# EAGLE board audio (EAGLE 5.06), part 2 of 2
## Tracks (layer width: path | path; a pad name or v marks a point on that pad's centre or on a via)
GND  (via drill 0.8)  (1 unrouted)
  Top 0.254: v49.37,12.53 49.02,12.53 C25.2 48.86,12.69 48.1,12.69
  Top 0.305: 13.49,32.85 13.65,32.85 14.28,33.49 15.87,33.49 15.87,31.9 14.44,31.9 13.65,32.7 | 64.61,42.06 64.61,40 | 72.54,17.46 | 72.54,17.46 73.02,16.98 | 40.16,12.38 40.32,12.38 40.16,12.38 | 40.16,12.38 40,12.22 | 40.16,12.38 40,12.53
  Top 0.406: 71.75,27.46 70.48,27.46 70.32,27.3 70.32,26.35 70.64,26.03 | 26.66,6.5 | C40.2 26.66,6.5 | 70.64,26.03 | 72.7,23.96 70.64,26.03 | 73.02,16.98 75.56,16.98 75.56,16.03 | 25.39,0.47 | 22.38,7.45 22.38,6.66 | 22.38,6.66 22.38,3.49 | 22.38,3.49 | 22.38,3.49 25.39,0.47 | 22.38,3.49 22.38,0.47 | 22.38,6.66 22.86,7.14 | 22.38,6.66 21.74,7.3 | R19.1 43.18,12.38 43.02,12.38 | v39.37,12.38 40.32,12.38 43.02,12.38 | 43.02,12.38 44.92,12.38 45.4,11.9 47.3,11.9 48.1,12.69 48.1,13.33 59.05,13.33 | C41.1 50,19.68 IC7.1 49.11,19.62 v49.53,19.2
  Top 0.61: 31.59,38.09 31.59,30.95 30.79,30.16 | 30.79,30.16 | 30.79,30.16 30.63,30 28.25,30 28.25,32.85 30.63,32.85 31.11,33.33 | 47.78,42.06 47.78,40.32 47.94,40.16 51.27,40.16 51.27,42.54 51.75,43.01 | IC2.8 28.99,31.32 28.89,31.43 IC2.7 29.05,31.43 28.99,31.48 IC2.6 30.63,32.7 31.11,33.17 31.11,33.33 | 15.08,32.85 C3.2 | 15.08,32.85 | 8.57,32.85 8.41,32.85 7.77,33.49 | 8.57,32.85 9.2,32.85 | 9.2,32.85 13.49,32.85 15.08,32.85 | 31.11,42.7 31.11,40 | 31.11,40 31.11,33.33 | 50.64,41.11 50.64,41.27 48.89,43.01 51.75,43.01 | 51.75,43.01 63.65,43.01 64.61,42.06 65.4,41.27 C37.2 | C37.2 65.4,40.47 | C17.2 41.4,20.5 41.43,20.47 41.91,20.95 IC7.7 | IC6.5 IC6.12 72.23,28.09 I2C.2 70.96,26.66 73.18,24.44 | IC6.5 72.23,36.66 | 72.23,36.66 | 74.77,36.51 | 74.77,36.51 IC6.3 IC6.2 | IC6.5 74.71,36.56 74.77,36.51 | IC6.2 76.14,36.56 76.19,36.51 | 77.31,36.51 | 77.31,36.51 IC6.1 78.68,36.56 79.21,36.35 C13.1 79.21,36.98 | IC6.2 77.25,36.56 77.31,36.51 | C37.2 65.4,43.01 80.64,43.01 81.12,42.54 81.12,36.19 | 73.18,24.44 IC8.16 | 73.18,24.44 72.7,23.96 72.54,23.81 72.54,17.46 72.54,16.82 | 72.54,16.82 72.54,15.55 | 72.54,15.55 IC8.9 74.77,15.55 | 72.54,16.82 IC8.10 | 72.54,15.55 IC8.8 | 74.77,15.55 C18.- | 74.77,15.55 | R19.1 43.49,11.74 | 40.79,0.79 40.64,0.95 40.16,0.47 25.39,0.47 | C20.2 31.08,3.67 | 3.01,33.97 1.27,33.97 | 3.01,33.97 8.09,33.97 9.2,32.85 | 8.57,32.85 1.9,32.85 1.11,32.06 | 3.01,33.97 1.9,33.97 1.27,34.6 | 81.12,32.22 80.48,31.58 79.21,31.58 79.21,30.47 81.12,30.47 81.43,30.79 81.43,42.38 80.64,43.17 0.95,43.17 0.31,42.54 0.31,19.36 0.79,18.88 4.6,18.88 4.92,19.2 4.92,21.27 4.6,21.58 1.42,21.58 0.47,22.54 | 81.12,35.39 80.32,36.19 77.78,36.19 77.31,35.71
  Top 0.61: 26.98,42.7 26.98,42.06 28.41,40.63 30.47,40.63 31.11,40
  Top 0.813: R8.1 50.64,41.11 | C13.1 80.51,36.79 81.12,36.19 81.12,35.39 81.12,32.22 81.12,31.74 80.48,31.11 80,31.11 79.98,31.08 C12.2 | U$1.P$2 1.27,20.31 0.63,20.95 | 0.63,20.95 | 0.63,20.95 0.47,21.11 0.47,22.54 0.47,27.14 0.95,27.62 0.95,27.46 | 46.64,10.98 46.67,10.95 48.39,12.66 C25.2 | 26.82,6.5 26.35,7.45 22.38,7.45 | 22.06,7.77 22.38,7.45 | 22.38,7.45 16.35,7.45 15.87,7.93 15.87,9.99 | 24.92,7.77 26.03,6.66 26.03,5.87 27.78,5.87 28.57,5.07
  Top 1.016: 6.19,39.84 6.19,38.41 6.03,38.25 1.74,38.25 0.79,37.3 | C25.2 48.89,13.01 | 48.89,13.01 | 48.89,13.01 56.19,13.01 | 56.19,13.01 58.41,13.01 R24.1 | R24.1 | R24.1 | 56.19,13.01 C26.2
  Top 1.27: C32.2 37.62,42.7 | 10.63,27.46 C34.+ C33.- 10.63,11.58 C35.- | C19.1 29.2,3.96 28.89,4.28 28.89,6.5 | C40.2 26.79,6.47 26.82,6.5 28.89,6.5 | C22.2 32.35,11.71 28.89,8.25 28.89,6.5 | 40.79,0.79 46.67,0.79 | 46.67,0.79 48.26,0.79 | 46.67,0.79 58.26,0.79 59.21,1.74 | 59.21,1.74 | 59.21,1.74 59.37,1.9 59.37,3.8 59.53,3.96 64.77,3.96
  Top 1.422: 7.77,33.49 AF_IN1.1 0.79,33.49 | 0.79,33.49 0.79,27.46 0.95,27.46 AF_IN2.1 10.63,27.46 11.74,27.46 12.54,26.66 14.76,26.66 | 37.62,42.7 31.11,42.7 26.98,42.7 1.11,42.7 0.79,42.38 0.79,37.3 0.79,33.49 | 48.41,40.95 48.41,42.7 37.78,42.7 37.62,42.54 C32.2 | 48.41,40.95 C6.1 | R8.1 48.42,40.94 48.41,40.95 | C17.2 41.27,20.47 40.16,20.47 | C17.2 | 40.16,20.47 C16.- | TR1.2 16.35,26.66 14.76,26.66 | C22.2 36.19,11.74 36.83,12.38 v39.37,12.38 | R19.1 44.77,11.73 45.56,10.95 46.19,10.95 | 19.68,7.77 18.57,7.77 16.27,10.07 | 19.68,7.77 20.79,7.77 | 20.79,7.77 22.06,7.77 | L1.5 69.37,6.18 74.77,11.58 C18.- | L1.5 | 40.16,20.47 | v40,18.41 40.16,20.47 | 14.76,26.66 22.38,26.66 22.7,26.35 22.7,22.85 | 22.7,22.85 22.7,21.74 26.51,17.93 26.51,17.61 21.9,17.61 | 16.03,17.61 21.9,17.61 | 16.03,17.61 13.49,17.61 | 16.27,10.07 14.92,11.42 C35.- | C35.- | 16.27,10.07 16.35,10.15 | 16.35,10.15 C36.- | 16.35,10.15 | v39.37,12.38 38.73,13.01 30.79,13.01 25.55,7.77 | 20.79,7.77 24.92,7.77 25.55,7.77 | 25.55,7.77 25.87,7.77 | 19.68,7.77 19.2,7.77 14.76,12.22 14.76,16.34 16.03,17.61 | 22.7,21.11 22.7,22.85 | 22.7,18.41 22.7,21.11 | 22.7,18.41 22.7,17.93 | 21.58,22.06 21.74,22.06 22.7,21.11 | 21.9,17.61 22.7,18.41 | 29.2,3.49 | C19.1 29.2,3.49 | C20.2 29.39,3.67 29.2,3.49 | v39.37,12.38 | v39.37,12.38 38.57,11.58 34.76,11.58 33.97,10.79 | 33.97,10.79 | 33.97,10.79 33.81,10.63 33.81,9.52 30.47,9.52
  Bottom 0.254: v39.37,12.38 39.37,17.61 v40,18.41 | v49.53,19.2 49.53,12.69 v49.37,12.53
N$1
  Top 1.676: C1.- | AF_IN1.2 C1.-
N$2
  Top 1.676: AF_IN2.2 6.82,30 C2.- 2.85,31.11 AF_IN2.2
N$3
  Top 1.016: 12.54,39.2 | 12.54,39.2 D1.C 12.58,39.32 14.12,37.78 R1.1 | D2.A 12.42,39.32 12.54,39.2
  Top 1.422: C1.+ | C1.+ 9.04,39.36 10.63,39.36 | 10.63,39.36 | 10.63,39.36 D2.A
N$4
  Top 0.406: 16.5,40.79 16.35,40.79 15.55,40 14.12,40
  Top 0.61: IC1.2 19.84,40.32 20,40.47 22K.1 19.84,40.47 19.68,40.32 19.68,40.79 16.5,40.79 14.92,40.79 R1.2 | R1.2 | R1.2
N$5
  Top 0.406: 29.84,39.36 27.78,39.36 27.62,39.36 26.03,40.95
  Top 0.61: 25.87,40.95 26.19,40.95 27.78,39.36
N$6
  Top 0.61: IC1.6 18.57,29.84 R4.1
  Top 1.422: R4.1 R3.2
N$7
  Top 0.254: 19.68,32.7 19.68,31.43 21.11,30 21.43,29.68
  Top 0.406: IC1.7 19.84,31.43 21.27,30 R4.2
  Top 0.61: IC2.2 27.46,37.78 26.98,37.3 26.98,32.22 | 26.98,32.22 24.76,30 23.17,30 | R4.2 22.54,30 23.17,30 | 23.17,30 21.27,30 21.11,30 21.11,28.73 24.92,28.73 26.98,30.79 26.98,32.22
N$8
  Top 1.27: 10.63,31.11 10.68,31.15 D3.C 12.54,31.11 13.97,29.67 R3.1 | 10.63,31.11 | 10.63,31.11 D4.A | C2.+ 10.63,31.11
N$9
  Top 0.61: POT.1 | IC6.6 70.96,38.25 POT.1
N$10
  Top 0.61: 44.76,18.09 44.76,19.68
N$11
  Top 0.305: 47.3,29.04 46.83,28.57
  Top 0.61: C5.1 R27.2 47.46,27.77 47.3,27.93 47.3,29.04 | 47.3,29.04 IC3.3 | 47.3,29.04 47.3,28.89 47.78,28.41
N$12
  Top 0.61: IC2.12 33.33,33.97 32.86,34.44 32.86,37.3 33.33,37.78 35.08,37.78 | 35.08,37.78 IC2.15 | C4.1 40.95,35.71 38.89,37.78 35.08,37.78
N$13
  Top 0.406: 11.27,31.74 11.58,31.74 | 11.27,31.74 8.89,31.74 8.73,31.58 8.73,29.68 8.89,29.52 12.38,29.52 | 12.38,29.52 13.33,29.52 | 11.27,31.74 13.33,31.74 13.33,31.43 14.6,30.16 14.6,28.57 13.33,28.57 12.38,29.52
N$14
  Top 0.813: R11.1 56.35,23.65 52.38,23.65 49.85,26.18 50.01,25.88
  Top 1.422: R9.2 50.01,25.88 R10.1 | R11.1 57.49,24.79 C7.2
N$15
  Top 0.254: 57.15,29.36 | 57.15,29.36 58.26,28.25 58.26,26.82 58.1,26.66 56.51,26.66 | 57.15,29.04 57.15,28.89 56.67,28.41 56.67,26.82
  Top 0.61: C8.1 55.27,25.42 56.51,26.66 R11.2 | R11.2 | IC4.2 57.15,29.36 57.15,29.04 57.15,27.93 R11.2
N$16  (via drill 0.6)
  Top 0.254: 53.18,38.09 53.34,37.46 | v53.18,37.14 53.34,37.46 | 53.34,37.46
  Top 0.61: 55.88,30.16 55.88,29.2 55.56,28.89 | 55.88,30.16 IC4.1 55.5,30.25 v54.76,29.2 | 54.92,28.25 55.56,28.89 | 55.56,28.89 55.56,27.62 55.24,27.3 | 55.24,27.3 | 55.24,27.3 55.08,27.14 52.22,27.14 52.22,28.41 53.34,28.41 55.88,30.95 55.88,30.16
  Top 1.27: R12.1 53.18,37.3 53.18,38.09 v53.18,37.14
  Top 1.422: C8.2 54.92,28.25 54.45,27.77 R10.2
  Bottom 0.254: v54.76,29.2 54.76,34.6 53.18,36.19 v53.18,37.14
N$17
  Top 0.61: IC5.7 36.57,23.23 36.67,23.33 | 36.67,23.33 IC5.6 | 36.19,23.65 36.35,23.65 36.67,23.33
  Top 1.422: C11.+ 36.19,23.65
N$19
  Top 0.406: 61.27,37.14 58.89,37.14 58.41,36.66 | 58.41,36.82 57.94,37.3
  Top 0.61: IC4.6 58.41,36.66 58.41,36.82 58.41,37.62 58.57,37.78
  Top 1.422: 58.57,37.78 | 58.57,37.78 C10.1 | R14.2 58.58,37.78 58.57,37.78
N$20
  Top 1.016: C11.- 35.71,28.25 33.17,25.71 28.73,25.71 TR1.1 | TR1.1 | TR1.1
N$21
  Top 0.406: 60.8,33.81 61.11,34.12
N$22
  Top 0.61: 35.08,36.51 IC2.14 38.41,36.51 38.89,36.03 39.05,35.87 39.05,32.7 | 39.05,32.7 39.05,26.5 38.25,25.71 | 38.25,25.71 37.94,25.39 IC5.5 | 38.25,25.71 38.25,31.9 39.05,32.7
N$23
  Top 1.422: AF_OUT.1 20.95,14.76 20.79,14.92 TR1.3 | TR1.3 | TR1.3
N$24
  Top 1.422: AF_OUT.2 | TR1.4 23.65,14.92 23.49,14.76 23.49,10.79 | 23.49,10.79 | AF_OUT.2 23.49,10.79
N$25
  Top 0.61: SPKR.2 43.97,19.62 IC7.8
N$26
  Top 0.406: 75.88,23.17 IC8.15 | 75.88,23.17 | 75.88,23.17 76.04,23.33 | 76.04,23.33 76.35,23.65 76.35,25.87 76.35,26.5 I2C.4 | 76.04,23.33 73.97,23.33 | 75.88,23.17 | 75.88,23.17 75.72,23.01 73.97,23.01
  Top 0.61: IC6.14 74.77,28.09 75.56,27.3 | I2C.4 75.56,27.3 | 75.56,27.3 75.56,26.66 76.35,25.87 76.51,26.03 76.51,27.14 74.77,28.89
N$27
  Top 0.61: C14.+ 66.35,32.38 66.51,32.22 | 66.51,32.22 67.15,31.58 67.15,30.79 | 67.15,30.79 67.15,29.04 67.62,28.57 70.48,28.57 70.96,29.04 70.96,30.47 | 70.96,30.47 | 70.96,30.47 IC6.11 | 66.51,32.22 65.72,33.01 64.92,33.01 64.92,31.74 66.19,31.74 67.15,30.79
N$28
  Top 0.61: 64.77,29.84 C14.- | 64.77,29.84 61.91,26.98 61.91,23.81 61.27,23.17 | 64.77,29.84 | 61.27,23.17 | 61.27,23.17 61.11,23.01 58.89,23.01 | 58.88,22.05 58.89,22.06 58.89,22.69 | 58.89,23.01 58.89,22.69 | 64.77,29.84 | 64.77,29.84 65.24,30.31 65.4,30.31 65.4,29.52 | 60,22.85 59.53,22.38 59.53,22.69 58.89,22.69 | R15.1 57.77,21.89 58.89,23.01
N$29
  Top 0.305: 51.59,22.54 55.56,22.54 55.56,21.27
  Top 0.406: 54.92,21.89 54.93,21.89 55.56,21.27 57.3,19.52 57.3,19.37 R15.2
  Top 0.61: IC7.4 50.64,23.49 51.59,22.54 52.07,22.06 52.7,21.9
  Top 1.422: R16.2 | R16.2 | R16.2 54.73,21.87 | R16.2 54.92,21.89 54.92,21.9 | C15.2 54.74,21.87 R16.2
N$30  (via drill 0.8)
  Top 0.61: 73.5,30.31 IC6.13 | 73.5,30.31 I2C.3 73.5,26.66 v74.13,25.87 | 73.5,30.31 | v74.13,25.87 | v66.19,25.39 66.19,23.17 66.35,23.17 | 67.15,23.17 66.35,23.17 | 67.15,23.17 IC8.2 | 66.35,23.17 66.03,23.17 65.88,23.33 65.88,25.55 66.03,25.71 66.51,25.71 66.51,23.81 67.15,23.17
  Bottom 0.254: v74.13,25.87 67.62,25.87 v66.19,25.39
N$31  (1 unrouted)
  Top 0.406: SPKR.1 46.98,18.25 47.46,17.77 47.78,17.77 | 47.78,17.77 48.26,17.77 | 48.26,17.77 51.4,17.77 C15.1 54.74,19.07 R16.1 | 46.35,19.68 48.26,17.77 | 46.35,19.2 47.78,17.77 | 47.78,17.77
  Top 0.61: IC7.5 45.56,23.49 46.35,22.69 46.35,19.68 46.35,19.2 46.35,18.41 SPKR.1
  Top 1.27: 46.51,18.41 | 46.51,18.41 46.83,18.09
N$32
  Top 0.406: C41.2 49.42,21.26 IC7.2
  Top 0.61: 49.05,20.95 | IC7.2 49.05,20.95 | IC7.3 49.11,21.01 49.05,20.95
N$33
  Top 0.61: POT.3 | IC6.8 68.42,39.84 POT.3
N$34
  Top 0.61: POT.2 | IC6.7 69.69,39.52 70.16,40 | 70.16,40 POT.2 | 70.16,40 70.16,40.63 70.8,40.63 70.8,40.47 70.64,40.32
N$35
  Top 0.305: 50.32,2.37 50.16,2.53 arc119 47.62,2.53
N$36  (via drill 3.2)
  other vias: 3.17,3.01
N$37
  Top 0.406: 51.75,17.93 52.22,17.93 52.07,18.09 52.07,18.25
N$38
  Top 1.422: L1.1 64.92,6.18 Q2.1 | L1.1
N$39
  Top 1.422: C20.1 30.95,6.34 30.95,6.18 32.7,6.18 | 32.7,6.18 Q1.1 | C19.2 32.76,6.25 32.7,6.18
N$40
  Top 0.61: R25.2 56.03,6.5 56.03,6.66 56.5,6.19 56.5,6.18 55.25,6.18 55.24,6.18
  Top 0.813: 53.97,8.88 | 53.97,8.88 C24.1 | 53.97,8.88 53.49,8.4 T2.1 53.49,6.82 54.13,6.18 Q2.2
  Top 1.016: Q2.2 55.24,6.18 R25.2 | R24.2 58.41,8.09 56.5,6.18
N$41
  Top 0.406: 38.89,9.68 39.68,10.47 39.84,10.63
  Top 0.813: 38.89,8.88 T1.2 | 38.89,8.88 38.89,9.68 | R22.1 41.27,11.11 40.79,10.63 39.84,10.63 | C21.2 38.89,8.88
  Top 1.422: C21.2 38.41,8.88 38.38,8.91 C22.1
N$42
  Top 0.305: 40,2.22 39.84,2.37
N$43
  Top 0.305: 57.3,2.37 57.46,2.53 57.46,3.8 57.15,4.12 54.29,4.12 53.34,3.17
N$44
  Top 0.813: 51.11,8.88 | 51.11,8.88 C24.2 | T2.2 51.59,8.4 51.11,8.88
  Top 1.422: 50.98,9.86 C25.1 | 50.98,9.86 51.11,9.99 R26.1 | 51.11,8.88 51.11,9.73 50.98,9.86
N$45  (via drill 0.8)
  Top 0.254: 37.94,19.84 37.14,20.63 32.38,20.63 31.43,20.63 v30.79,21.11
  Top 0.406: 50.8,31.74 51.11,31.74 | 50.8,31.74 49.68,31.74 49.21,31.27 48.41,31.27 48.41,29.36 52.54,29.36 54.45,31.27 | C28.1 50.8,31.58 50.95,31.58 | IC4.4 59.69,31.11 59.69,32.06 59.53,32.06 | 55.4,32.06 55.24,32.06 54.45,31.27 | 55.4,32.06 59.21,32.06 | 59.21,32.06 59.53,32.06 | C39.- 54.45,31.27 | 59.53,32.06 62.7,32.06 62.7,30.95 61.11,29.36 | 61.11,29.36 | 61.11,29.36 60.96,29.2 59.53,29.2 59.53,31.74 59.21,32.06 | 50.8,31.74 54.45,31.74 54.76,32.06 55.4,32.06
  Top 0.61: 17.62,35.87 18.25,35.24 25.55,35.24 25.71,35.39 25.71,37.93 26.03,38.25 26.03,38.73 25.87,38.89 24.44,38.89 22.7,37.14 22.7,36.51 21.9,35.71 | IC1.4 17.3,36.19 17.77,35.71 21.9,35.71 | C27.1 23.33,35.71 21.9,35.71 | IC3.4 49.94,30.25 50.8,31.11 | C29.1 59.71,31.14 59.69,31.11 | 37.94,19.36 37.94,19.84 37.46,20.31 33.65,20.31 | 37.94,19.36 IC5.4 | C30.1 32.38,20.47 32.54,20.31 33.65,20.31 | 33.65,20.31 32.86,19.52 31.9,19.52 30.32,21.11 30.32,21.42 32.86,21.42 33.81,20.47 | 31.11,20.95 31.59,20.95 31.74,20.95 | 37.94,19.36 37.94,20 37.14,20.79 | 37.14,20.79 33.17,20.79 | 37.14,20.79 36.83,21.11 32.86,21.11
  Top 0.813: C28.1 50.93,31.14 50.95,31.11 v50.48,30 | 7.69,23.09 v8.09,22.22
  Top 1.016: v24.44,38.41 24.44,36.19 24.28,36.03 | C31.- 25.24,38.25 v25.55,38.41 | v30.79,21.11 31.11,21.11 31.9,20.31 32.06,20.31 32.38,20.63 31.9,20.63 31.59,20.95
  Top 1.27: 23.33,36.19 | 23.33,36.19 C27.1 | C31.- 24.28,36.03 23.49,36.03 23.33,36.19 | C28.1 50.8,31.11 50.95,31.27 C39.- | U$1.P$3 | U$1.P$3 | U$1.P$3 4.44,25.08 C34.- 8.09,23.49 7.69,23.09 v6.82,22.22
  Top 1.422: 8.09,25.23 2.54,25.23 2.06,24.76 2.06,23.65 2.38,23.33 5.71,23.33 v6.82,22.22 8.25,22.22 8.25,25.23
  Bottom 0.254: v6.82,22.22 v8.09,22.22 | v8.09,22.22 8.33,22.46 | 8.33,22.46 v24.44,38.41 | v25.55,38.41 42.22,38.41 v50.48,30 | 8.33,22.46 8.33,22.45 | v30.79,21.11 9.36,21.42 v8.09,22.22
N$46
  Top 0.813: 41.27,8.88 40.79,8.4 T1.1 41.12,6.97 41.91,6.18
  Top 1.016: Q1.2 41.91,6.18 R20.1
  Top 1.27: C21.1 41.27,8.88 41.28,8.89 R19.2
N$47
  Top 0.61: IC8.13 76.67,20.63 77.15,20.15 | 77.15,20.15 77.78,19.52 | 77.78,19.52 OC.3 | 77.78,19.52 78.42,18.88 79.85,18.88 80.16,19.2 80.16,19.84 79.85,20.15 77.15,20.15
N$48
  Top 0.406: IC8.5 66.51,19.36 66.35,19.2 | 66.35,19.2 66.67,19.52 69.37,19.52 69.37,19.2 66.35,19.2 | 47.78,14.28 47.62,14.28 46.83,13.49 | 61.27,14.28 61.43,14.28 66.35,19.2
  Top 0.61: C23.2 46.19,13.96 46.51,14.28 | 46.51,14.28 47.78,14.28 61.27,14.28 | 46.51,14.28 40.48,14.28 40.48,13.33
  Top 1.422: 46.19,13.8 | C23.2 46.19,13.8 | R22.2 46.19,13.8
N$49
  Top 0.254: R26.2 54.45,11.11 54.61,10.95
  Top 0.305: 55.56,10.15 56.99,10.15 57.3,9.84 56.99,9.52 56.99,8.57 55.4,8.57 55.4,9.99
  Top 0.406: 60.48,9.99 60.35,9.86 56.7,9.86 56.43,9.6 56.19,9.36 | 60,9.84 60.64,9.84 60.64,11.9 | 60,9.84 57.3,9.84 56.83,9.84 | 60.48,10.47 60.48,10.31 60,9.84
  Top 0.61: 60.48,9.99 60.48,10.47 60.48,11.9 66.67,18.09 IC8.6 68.73,18.09 | 54.61,10.95 56.19,9.36 | C26.1 56.22,9.39 56.43,9.6
N$50
  Top 1.016: 78.1,33.33 78.1,34.28
N$51
  Top 1.016: 77.62,33.65 77.46,33.65 76.35,32.54
N$52
  Top 0.61: OC.1 | IC8.11 75.88,18.09 78.26,15.71 | 78.26,15.71 79.05,14.92 | 79.05,14.92 OC.1 | 79.05,14.92 80.16,14.92 80.16,13.8 80,13.65 79.21,13.65 78.26,14.6 78.26,15.71
N$53
  Top 0.61: D5.A 78.21,21.95 78.26,21.9 76.99,21.9 | IC8.14 74.77,21.9 | 74.77,21.9 76.99,21.9 | 74.77,21.9 76.83,21.9 77.46,22.54 80,22.54 80.16,22.38 80.16,21.74 79.85,21.42 77.46,21.42 76.99,21.9
  Top 1.27: D5.A 78.1,22.06 OC.4
N$54
  Top 0.406: 41.91,29.52 41.91,29.68
N$55  (via drill 3.2)
  other vias: 3.17,40.47
N$56  (via drill 3.2)
  other vias: 78.42,3.01
N$57  (via drill 3.2)
  other vias: 78.42,40.47
N$58
  Top 0.61: 77.94,19.68 79.69,19.68
N$59
  Top 0.254: 63.02,20.15 63.02,21.58 63.18,21.74 65.72,21.74 | 60,19.84 59.69,19.52
  Top 0.406: R18.1 63.66,20.8 63.02,20.15 62.7,19.84 62.54,19.84 | 62.54,19.84 64.13,19.84 66.03,21.74 69.37,21.74 69.37,22.06 66.03,22.06 65.72,21.74 65.4,21.42 | 62.54,19.84 60,19.84 59.53,19.84 59.53,19.68 | 59.05,16.66 59.53,17.14
  Top 0.61: IC2.10 35.14,30.21 35.08,30.16 | R18.1 64.6,20.48 64.61,20.47 66.03,21.9 IC8.3 | 27.3,27.3 25.87,25.87 25.87,23.65 33.49,16.03 38.57,16.03 39.21,16.66 59.05,16.66 59.53,16.66 59.53,18.88 59.53,19.68 | 27.3,27.3 | 27.3,27.3 27.46,27.46 32.38,27.46 34.29,29.36 | 35.08,30.16 IC2.9 | 34.29,29.36 35.08,30.16 | 34.29,29.36 34.29,31.43 36.03,31.43 36.03,30 34.76,30
N$60
  Top 0.61: 78.42,19.2 80,19.2
N$61
  Top 0.61: 78.26,17.46 79.85,17.46 80.16,17.14 80.16,16.66 79.85,16.34 79.37,16.34 78.73,16.98 | IC8.12 76.35,19.36 78.73,16.98 | 78.73,16.98 OC.2
N$62
  Top 0.61: 79.85,16.98 79.53,16.66
N$63
  Top 0.61: 78.58,14.92 79.53,13.96
N$64
  Top 0.61: 79.85,13.96 79.85,14.6
N$65
  Top 0.61: 77.31,30.31 77.31,28.25 77.94,27.62
N$66
  Top 0.61: 79.21,28.89 80.8,28.89 81.27,28.41 81.27,24.44 80.96,24.12 77.62,24.12 77.46,24.28 77.46,28.09
N$67
  Top 1.016: 77.78,28.25 77.78,29.68
N$68
  Top 1.016: 78.1,26.03 78.1,27.46
N$69
  Top 1.016: 80,25.87 80,27.46
N$70
  Top 0.61: 73.5,27.46 74.45,26.5 74.45,25.55 73.97,25.55 73.02,26.5 73.02,27.14 73.34,27.46
N$71
  Top 0.61: 68.42,39.52 68.42,40.95 68.26,41.11 67.46,41.11 67.3,40.95 67.3,40.32 68.42,39.2
N$72
  Top 0.61: 69.69,39.36 69.69,40.95 69.84,41.11 70.96,41.11 71.11,40.95 71.11,40.16 69.69,38.73
N$73
  Top 0.61: 67.78,40.79 67.78,40.47
N$74
  Top 0.61: 68.1,40.79 68.1,40.63
N$75
  Top 0.61: 72.54,39.84 72.54,40.95 72.7,41.11 73.66,41.11 73.81,40.95 73.81,39.68 73.66,39.52 72.23,39.52
N$76
  Top 0.61: 73.02,40.79 73.02,39.68
N$77
  Top 0.61: 73.34,40.79 73.34,39.84
N$78
  Top 0.61: 46.03,17.77 46.03,22.69
N$79
  Top 0.406: 55.08,40.79 55.56,40.79
N$80
  Top 0.406: 60.16,40 63.81,40 63.81,41.27 63.34,41.74 60.48,41.74 60.16,42.06 59.53,42.06 | 55.24,40.47 55.4,40.47 | 55.24,40.47 56.99,40.47 56.99,41.74 56.19,41.74 | 56.19,41.11 56.35,40.95 57.46,42.06 57.78,42.06 | 60.8,41.27 60.48,41.27 59.69,42.06 59.53,42.06 | 57.78,42.06 59.53,42.06 | 57.78,42.06 52.38,42.06 52.38,40.63 55.08,40.63 55.24,40.47 | 55.24,40.47 55.56,40.63
  Top 0.61: 60.8,41.27 R14.1
  Top 1.27: R13.1 56.19,41.11 56.03,41.27 55.72,41.42 R12.2
  Top 1.422: R14.1 | R14.1 | C9.2 60.83,40.6 R14.1
N$81
  Top 0.406: 60.32,41.43 63.34,41.43
N$82
  Top 0.254: 60,41.59 60,40
N$83  (via drill 0.8)
  Top 0.254: 59.69,39.2 59.37,39.52 59.37,41.43 57.78,41.43 57.78,39.52 | 57.15,36.19 56.03,37.3
  Top 0.305: 56.35,38.09 56.83,38.57 57.78,39.52 58.1,39.84 58.57,40.32 | 37.46,34.92 37.46,34.12
  Top 0.406: 67.15,38.73 | 67.15,38.73 66.67,39.2 59.69,39.2 59.53,39.2 | 59.53,39.2 59.37,39.2 58.57,40 58.57,40.47 | 58.57,40.47 | C10.2 58.57,40.47 | 59.53,39.2 57.46,39.2 56.83,38.57 | 58.1,39.84 57.94,39.84 57.3,39.2 | 57.3,39.2 56.67,38.57 55.08,38.57 54.92,38.41 54.92,38.09 | 54.92,38.09 54.92,37.46 55.08,37.3 56.51,37.3 | 54.92,38.09 54.92,38.57 55.56,39.2 57.3,39.2
  Top 0.61: 56.35,38.09 R13.2 56.35,37.93 | 58.57,40.32 C10.2 | IC4.7 57.15,36.19 57.15,36.51 56.51,37.3 56.51,37.62 56.35,37.78 56.35,37.93 | IC6.10 69.69,32.54 67.15,35.08 67.15,38.73 | IC2.13 37.14,35.24 37.46,34.92 v37.46,34.28 | v55.4,37.93 55.72,37.78 | 55.72,37.78 | 55.72,37.78 56.19,37.78 56.35,37.93
  Top 0.813: 37.46,34.12 37.46,33.81
  Bottom 0.254: v37.46,34.28 51.91,34.28 v55.4,37.93
N$84
  Top 1.016: 61.11,31.58 60,31.58
N$85
  Top 1.016: 60.32,29.68 60.32,31.11
N$86
  Top 1.016: 61.11,29.84 61.11,30.95
N$87
  Top 1.016: 60.8,29.52 62.07,30.79
N$88
  Top 0.254: 27.93,39.52 30,39.52 30,38.73 27.62,38.73 26.19,40.16
  Top 0.305: 22.22,41.11 22.38,41.27 22.22,41.27 | 22.22,41.11 22.22,39.68 21.11,38.57 | 22.22,41.27 22.22,41.11 | 22.22,41.27 26.19,41.27 27.93,39.52
  Top 0.61: IC1.1 21.11,38.09 22.14,39.13 | 22.14,39.13 23.01,40 23.01,40.01 22K.2 | 22.14,39.13 | IC2.1 27.62,39.05 26.51,40.16 26.19,40.16 23.33,40.16 22K.2 | 22K.2
N$89
  Top 0.61: 53.65,31.58 54.29,31.58
N$90
  Top 0.61: 52.38,29.68 53.81,31.11
N$91
  Top 0.61: 49.05,30.47 49.05,31.11
N$92
  Top 0.61: 52.22,30 52.86,30.63
N$93
  Top 0.61: 49.53,31.27 50.32,31.27
N$94
  Top 1.016: 53.81,28.25 55.56,30
N$95
  Top 0.305: 45.87,17.61 54.92,17.61 55.56,18.25 55.56,19.84 55.4,20 52.07,20 51.91,19.84 51.91,18.41
N$96
  Top 0.406: 46.03,26.03 46.03,24.6 47.46,24.6 47.46,26.19 46.51,26.19 46.03,26.66 | 41.59,29.84 41.59,31.27 46.19,31.27 46.19,29.2 46.03,29.04 | 41.59,29.84 41.75,29.68 | 41.59,29.84 41.59,29.52 41.75,29.36 45.72,29.36 46.03,29.04 | R9.1 46.52,25.55 46.03,26.03 | 46.03,26.03 46.03,26.66 | 46.03,26.66 46.03,29.04 | 46.03,29.04 IC3.2
  Top 0.61: 44.7,30.25 IC3.1 | IC3.2 44.7,30.25 | 44.7,30.25 44.6,30.16
  Top 1.422: R6.2 42.22,30.31 42.28,30.25 IC3.1
N$97
  Top 0.305: 47.78,28.57 48.26,28.57 48.26,26.98 46.83,26.98
N$98
  Top 0.305: 55.24,18.41 | 54.76,17.93 55.24,18.41
  Top 0.406: 54.76,17.93 55.24,18.41 | 54.76,17.93
N$99
  Top 0.305: 44.6,36.35 44.6,34.12 45.24,33.49 49.68,33.49 50.16,33.49
  Top 0.406: 53.97,33.97 | 53.49,33.49 53.97,33.97 | 53.49,33.49 | 53.49,33.49 53.34,33.33 49.84,33.33 49.68,33.49
N$100
  Top 0.61: 45.87,37.14 46.51,36.51 46.98,36.51 | 46.98,36.51 47.3,36.51 47.3,34.6 46.03,34.6 46.03,36.82 45.24,37.62 | 46.98,36.51 46.83,36.51 44.92,38.41
N$101
  Top 0.61: 46.98,36.03 46.35,36.03
N$102
  Top 0.61: 46.98,35.08 46.35,35.08
N$103
  Top 0.61: 53.81,39.36 53.81,36.82 53.65,36.66 52.7,36.66 52.54,36.82 52.54,39.36 53.81,39.36
N$104
  Top 0.305: 40.48,36.35 41.75,36.35 41.75,34.92 40.16,34.92 40.16,36.51
N$105
  Top 0.406: 59.05,39.52 59.05,40
N$106
  Top 0.813: 58.73,39.52 57.94,39.52
N$107
  Top 0.254: 56.99,38.57 56.99,36.98 57.46,36.51 57.46,34.44 56.99,34.44
N$108
  Top 0.406: 55.24,37.3 55.24,38.41
N$109
  Top 0.406: 45.08,38.25 45.08,38.89 43.65,38.89 43.65,37.3
N$110
  Top 0.406: 44.45,37.46 44.13,37.46 43.65,36.98
N$111
  Top 0.406: 43.18,32.38 48.41,32.38
N$112
  Top 0.406: 43.97,32.85 43.97,33.33
N$113
  Top 0.406: 44.13,32.85 44.13,33.17
N$114
  Top 0.406: 42.54,37.3 40.95,37.3 40.95,38.89 42.38,38.89 42.38,37.62
N$115
  Top 0.406: 41.75,33.17 41.75,32.22 41.27,32.22 40.64,31.58
N$116
  Top 0.406: 41.43,27.3 41.59,27.46
N$117
  Top 0.254: 40.48,28.57 45.24,28.57
  Top 0.406: R5.1 41.75,38.09 42.7,37.14 42.7,36.82 | 42.7,36.82 42.7,34.28 42.06,33.65 | 42.06,33.65 41.59,33.17 41.27,33.17 40.95,32.85 | 40.95,32.85 | C4.2 40.95,32.85 | 42.7,36.82 42.06,37.46 | 42.06,33.65 40.16,33.65 40.16,28.25 41.43,26.98 45.24,26.98 45.24,28.41
  Top 0.61: 40.48,29.04 41.27,28.25 42.06,28.25
  Top 0.813: 42.38,27.77 41.27,27.77 40.64,28.41 | 40.64,28.41 | 40.64,28.41 40.48,28.57 40.48,29.04 40.48,32.54 40.82,32.88 C4.2
  Top 1.422: R6.1 42.22,27.62 42.38,27.77 42.86,27.77 R27.1 C5.2
N$118
  Top 0.305: 45.87,18.57 45.87,23.01
N$119
  Top 0.61: 48.1,21.11 48.1,20.95 50,20.95 50,22.22 49.84,22.22 | 48.1,21.11 48.1,22.22 49.84,22.22 | 49.84,22.22 50.32,22.22 50.8,21.74 50.8,20.79 48.1,20.79 48.1,21.11
N$120
  Top 0.305: 51.91,22.06 51.91,21.11 55.56,21.11
N$121
  Top 0.813: 61.27,16.19 62.86,17.77
N$122
  Top 0.61: 43.18,19.68 43.18,18.09 43.65,17.61 44.29,17.61 44.76,18.09
N$123
  Top 0.61: 42.54,20.95 42.22,20.95 42.06,21.11 40.32,21.11 39.84,21.58 39.21,21.58 39.05,21.42 39.05,20.63 39.37,20.31 39.37,18.09 39.52,17.93 40.48,17.93 41.91,19.36 41.91,20.31 42.54,20.95
N$124
  Top 0.61: 40.64,18.88 41.43,19.68
N$125
  Top 0.61: 40.95,19.52 40.95,19.84
N$126  (via drill 0.8)
  Top 0.254: 39.52,40.47 40.95,40 41.75,40.47 v40.79,40.47 | IC6.15 76.04,32.06 77.15,33.17 79.05,33.17 v79.21,33.01
  Top 0.305: 42.06,25.71 42.06,25.39 40.95,25.39 | v40.79,25.39 40.95,25.39 | v42.22,25.39 | 40.95,25.39 v42.22,25.39
  Top 0.61: 44.6,24.76 42.22,24.76 | 44.6,24.76 44.6,24.92 44.76,24.92 | 44.76,24.92 44.6,24.76 | 44.76,24.92 44.76,25.55 44.6,25.71 42.54,25.71 42.7,25.55 42.7,25.08 41.91,24.28 41.91,23.01 | IC2.16 37.94,39.05 38.57,39.52 | C17.1 41.56,23.3 41.59,23.33 41.91,23.01 | 42.7,22.22 IC7.6 | 41.91,23.01 42.7,22.22 | IC6.15 76.04,31.9 76.83,32.7 | 76.83,32.7 77.15,33.01 v79.21,33.01 79.21,33.33 C13.2 | C16.+ 39.68,23.33 39.68,23.81 | 76.83,32.7 79.85,32.7 79.85,34.6 77.78,34.6 76.04,32.85 76.04,31.74 | 42.38,25.71 42.06,25.71 40.64,25.71 39.21,24.28 | 39.21,24.28 | 39.21,24.28 39.05,24.12 39.05,22.85 39.21,22.69 41.75,22.69 | 41.75,22.69 42.06,22.69 | 42.7,22.22 42.22,22.22 41.75,22.69 | 41.59,25.39 40.95,25.39 39.84,24.28
  Top 1.016: 39.68,23.81 40.48,23.81 41.03,24.36 | 41.03,24.36 v42.22,25.39 | 41.03,24.36 41.11,24.28 | v40.79,25.39 41.03,24.36
  Top 1.27: C32.1 37.62,39.52 38.57,39.52 39.52,40.47 R7.2 | C35.+ | U$2.P$1 7.77,11.74 C35.+ | C35.+ 8.09,11.74 v6.5,13.33
  Top 1.422: 41.11,23.49 41.27,23.33 C17.1 | C16.+ 41.11,23.49 | 41.11,23.49 | v6.5,13.33 8.25,13.33 8.25,10.79 2.06,10.79 2.06,13.33 v6.5,13.33
  Bottom 0.254: v40.79,40.47 v42.22,25.39 50,33.33 v79.21,33.01 | v6.5,13.33 28.89,13.33 v40.79,25.39
N$127
  Top 0.61: 43.02,25.23 44.45,25.23
N$128
  Top 0.254: 56.83,26.82 58.1,26.82
N$129
  Top 0.305: 57.94,28.25 57.3,28.89
N$130
  Top 0.305: 57.46,28.25 57.46,28.57
N$131
  Top 0.406: 13.49,28.89 12.54,29.84
N$132
  Top 0.254: 55.72,25.55 55.72,24.76 54.13,24.76 53.97,24.92 53.97,26.03 54.13,26.19 55.88,26.19
N$133
  Top 0.254: 58.26,29.84 58.26,29.2 59.21,28.25 59.21,26.82 59.37,26.66 60.64,26.66 60.8,26.82 60.8,27.46
N$134
  Top 0.406: 61.27,28.25 59.53,28.25
N$135
  Top 0.254: 44.92,39.68 45.08,39.68 | 44.92,39.68 44.76,39.68 44.6,39.84 44.6,41.11 44.76,41.27 46.51,41.27 46.67,41.11 46.67,39.68 | 45.4,39.68 44.92,39.68
N$136
  Top 0.406: 44.76,39.84 44.76,41.11
N$137
  Top 0.406: 46.51,40.16 46.51,40.95
N$138
  Top 0.406: 47.46,38.73 51.43,38.73 51.43,37.3 51.27,37.14 48.57,37.14 | 45.24,40.16 45.24,39.84 48.57,36.51
  Top 0.61: IC3.5 48.57,36.19 | 48.57,36.19 48.57,36.51 48.57,37.14 48.57,38.09 | 49.84,37.46 49.84,37.62 | 48.57,36.19 49.84,37.46 | 49.84,37.46 48.1,37.46 48.1,37.3 48.26,37.14
  Top 1.27: R8.2 48.58,38.1 48.57,38.09 48.54,38.12 C6.2 47.59,38.12 45.72,40 R7.1
N$139
  Top 0.61: 46.83,42.54 46.98,42.54 47.94,41.59
N$140
  Top 0.61: 81.27,31.58 81.27,31.27 80.64,30.63
N$141
  Top 0.406: 40.16,40 40.16,39.84 39.21,38.89 33.97,38.89 33.81,39.05 33.81,40.47 33.97,40.63 39.05,40.63 39.52,40.63
  Top 0.61: 39.21,39.05 40,39.84 43.49,39.84 43.49,41.11 39.52,41.11 39.05,40.63
N$142
  Top 0.305: 14.28,32.38 13.97,32.7
N$143  (via drill 0.8)  (3 unrouted)
  Top 0.254: 52.07,32.54 53.97,32.54 | 53.97,32.54 54.13,32.54 54.45,32.85 | 13.65,35.52 v13.65,35.24 | 53.97,32.54 54.29,32.54 54.61,32.85
  Top 0.305: 18.73,36.66 18.73,39.36 18.41,39.68 16.66,39.68 16.19,39.2 16.19,36.35 | 18.41,39.2 18.41,36.66 | 17.77,39.52 17.93,39.52 18.57,38.89 | 63.65,33.17 63.34,32.85 63.65,32.54 | 44.45,32.7 44.6,32.85 | 43.65,32.7 43.18,32.7 43.18,33.01 43.33,33.17 43.41,33.09 | 43.41,33.09
  Top 0.406: IC1.3 18.57,39.05 18.41,39.2 18.09,39.52 17.77,39.52 16.82,39.52 16.35,39.05 16.35,36.51 16.19,36.35 15.37,35.52 14.92,35.39 | 60,27.62 58.41,29.2 | 54.45,32.85 54.61,32.85 63.34,32.85 63.81,32.85 | 49.37,32.54 44.92,32.54 43.65,33.81 43.65,37.3 | 49.37,32.54 52.07,32.54 | R5.2 | 43.65,37.3 R5.2 | 43.65,37.3 43.65,32.85 v43.49,32.7 | 49.37,32.54 49.05,32.54 48.57,32.06 43.02,32.06 42.86,32.22 42.86,32.85 43.65,33.65 | v43.49,32.7 43.18,32.7 | v43.49,32.7 43.65,32.7 44.45,32.7 | 43.65,33.33 43.41,33.09 43.18,32.85 | 16.35,34.76 16.35,36.66 | 16.5,34.6 13.81,34.6
  Top 0.61: IC1.5 17.3,33.81 16.5,34.6 16.35,34.76 15.71,35.39 15.08,35.39 | 15.08,35.39 | C3.1 15.08,35.39 | IC3.6 46.13,35.45 46.03,35.55 IC3.7 46.03,36.98 44.76,38.25 44.6,38.09 R5.2 | 59.69,35.87 IC4.5 | 59.69,35.87 61.91,35.87 63.02,36.98 63.02,37.78 | 59.69,35.87 63.34,35.87 63.81,35.39 63.81,33.81 | 63.81,30.63 63.81,32.85 63.81,33.81 | 63.81,30.63 | 63.81,30.63 60.8,27.62 60,27.62 | IC6.9 68.42,32.06 65.88,34.6 65.88,37.3 65.4,37.78 C37.1 | 63.81,33.81 64.13,34.12 66.35,34.12
  Top 1.422: 10.63,34.6 | 10.63,34.6 D4.C 10.74,34.55 10.79,34.6 10.84,34.55 D3.A 12.54,34.92 | D2.C 10.63,34.6 | 10.63,34.6 | 12.54,34.92 | 12.54,34.92 D1.A 12.54,35.55 12.57,35.52 13.65,35.52 15.37,35.52 C3.1 | 12.54,34.92 | C9.1 63.02,37.78 63.05,37.8 C37.1
  Bottom 0.254: v43.49,32.7 16.19,32.7 v13.65,35.24
N$144
  Top 0.254: 12.38,38.57 13.97,36.98 15.55,36.98 15.55,38.57 13.81,38.57
N$145
  Top 0.406: 8.73,37.93 8.25,37.93 | 8.73,37.93 13.33,37.93 | 8.73,37.93 7.62,37.93 7.62,38.89 8.73,40 13.17,40
N$146
  Top 0.406: 13.97,37.3 | 12.54,38.73 13.97,37.3
N$147
  Top 0.406: 13.65,36.19 13.33,36.51 9.84,36.51 9.84,33.97 13.49,33.97 14.28,34.76
N$148
  Top 0.61: 13.81,36.03 16.19,36.03
N$149
  Top 0.813: 13.49,34.28 13.49,34.76 13.97,34.76
N$150
  Top 0.813: 15.87,35.71 15.87,35.39 16.03,35.24
N$151
  Top 0.813: 11.74,35.24 11.74,36.19
N$152
  Top 0.406: 14.12,41.27 21.11,41.27 21.11,40 20,38.89
N$153
  Top 0.406: 18.57,40.95 18.73,40.95 19.52,40.16 | 19.52,40.16 20,39.68 | 19.52,40.16 19.52,39.68 19.68,39.52
N$154
  Top 0.406: 20.47,39.84 20.47,39.68 20,39.2
N$155
  Top 0.406: 15.55,40.32 15.87,40.63
N$156
  Top 0.61: 51.11,24.76 48.89,24.76 48.89,26.03 49.37,26.5 49.37,28.41 50.8,28.41 50.8,26.35 53.34,23.81
N$157
  Top 1.016: 23.17,36.98 23.97,37.78
N$158
  Top 1.016: 23.97,36.98 23.65,36.98
N$159
  Top 0.61: 18.57,31.74 18.57,30.95 19.52,30
N$160
  Top 0.61: 19.52,29.04 19.52,28.73 16.19,28.73 16.19,30.16 17.93,30.16 18.57,30.79
N$161
  Top 0.305: 21.27,36.66 21.27,37.3 23.97,40
N$162
  Top 0.61: 21.11,33.01 21.11,33.65 21.43,33.97 25.55,33.97 25.71,33.81 25.71,33.01 23.97,31.27 21.43,31.27 21.11,31.58
N$163
  Top 0.61: 24.92,33.01 24.92,32.7 23.97,31.74
N$164
  Top 0.61: 24.76,32.85 24.6,32.85 23.97,32.22
N$165
  Top 1.016: 26.66,31.11 24.76,29.2 22.7,29.2
N$166
  Top 0.61: 21.43,37.78 23.33,39.68
N$167
  Top 0.61: 50.48,25.87 52.54,23.81
N$168
  Top 0.406: 36.67,35.08 34.29,35.08 34.29,35.39 37.62,35.39 37.94,35.08 37.94,33.49 37.78,33.33 37.14,33.33 36.98,33.49 36.98,34.6 36.51,35.08
N$169
  Top 0.406: 36.98,34.92 | 37.14,34.76 36.98,34.92
N$170
  Top 0.61: 35.55,30.31 35.55,31.27
N$171
  Top 0.61: 34.76,30.47 34.76,31.11
N$172
  Top 0.406: 51.75,4.76 52.22,4.28 | 45.08,4.76 41.11,4.76 T1.3 | 45.08,4.76 51.75,4.76 | 51.75,4.76 51.91,4.76 51.75,4.76 | 51.75,4.76 46.03,4.76 | 45.87,5.55 | 45.08,4.76 45.87,5.55 | 45.08,4.76 45.4,4.76 45.72,5.07 | T1.3
  Top 1.016: T1.3 38.89,3.8 R21.1
N$173
  Top 0.61: 31.43,23.96 33.65,23.96 33.65,23.49 33.17,23.49
N$174
  Top 0.61: 36.67,25.71 36.67,22.38 35.4,22.38 35.4,25.55 35.87,26.03 36.51,26.03
N$175
  Top 0.61: 35.71,22.85 36.35,22.85
N$176
  Top 0.61: 30.32,21.27 31.9,19.68
N$177
  Top 1.422: 13.97,7.93 13.97,9.2 13.65,9.2 13.01,8.57 2.06,8.57 2.06,7.93 13.97,7.93 | 13.97,7.93
N$178
  Top 1.016: 35.08,27.62 36.03,28.57 36.51,28.57 36.51,27.62 35.24,27.62
N$179
  Top 0.305: 33.49,26.19 28.09,26.19 27.62,25.71 27.62,24.28 28.73,24.28
N$180
  Top 0.254: 28.89,24.28 30.47,25.87
N$181
  Top 0.61: 29.68,25.55 28.73,24.6 27.93,24.6 27.93,25.71 28.09,25.71 28.25,25.87
N$182
  Top 0.61: 29.68,25.87 29.52,25.87 28.89,25.23
N$183
  Top 0.61: 49.84,25.08 50.64,25.08
N$184
  Top 0.61: 56.83,24.44 56.83,25.39 60.64,25.39 60.64,24.12 56.99,24.12
N$185
  Top 0.61: 64.29,29.36 65.4,29.36
N$186
  Top 0.406: 62.23,21.9 62.23,20.63 60.64,20.63 60.64,21.9 61.91,21.9
N$187
  Top 0.61: 67.94,24.6 67.94,26.98
N$188
  Top 0.61: 67.78,24.44 67.78,24.6 67.78,26.19 66.83,27.14
N$189
  Top 0.61: 63.34,23.01 64.45,23.01 64.61,23.17 64.61,26.5
N$190
  Top 0.61: 64.77,26.82 67.46,26.82
N$191
  Top 1.016: 68.57,25.55 | 68.57,25.55 69.37,24.76
N$192
  Top 0.406: 65.08,21.58 63.34,21.58 | 65.08,21.58 65.4,21.58 | 64.61,21.11 65.08,21.58
N$193
  Top 0.254: 57.62,9.04 57.62,8.09 57.15,7.61 55.08,7.61 54.61,8.09
N$194
  Top 0.305: 66.19,40 66.19,41.43 66.99,42.22 74.29,42.22 75.08,41.43 75.08,39.05 73.5,37.46
N$195
  Top 0.61: 65.24,41.9 64.29,42.86
N$196
  Top 0.61: 64.92,41.27 64.92,43.01
N$197
  Top 0.61: 65.88,41.43 65.88,41.27 | 65.88,41.43 65.88,42.86 | 65.88,41.43 66.83,42.38
N$198
  Top 0.813: 66.03,42.54 80.8,42.54
N$199
  Top 0.406: 57.94,38.41 61.43,38.41
N$200
  Top 0.406: 56.83,37.3 56.83,37.62
N$201
  Top 0.406: 55.88,37.62 55.08,37.62
N$202
  Top 0.406: 59.69,36.35 59.84,36.35 60,36.19 | 60,36.19 60.16,36.03 | 60,36.19 61.75,36.19 62.38,36.82
N$203
  Top 0.61: 59.69,35.24 59.69,36.19 | 59.69,35.24 59.69,34.76 | 59.69,35.24 | 60.48,36.03 59.69,35.24
N$204
  Top 0.61: 65.08,32.06 66.35,32.06
N$205
  Top 0.61: 65.08,32.54 65.88,32.54
N$206
  Top 0.254: 62.23,36.82 62.23,38.57 66.19,38.57 66.19,34.44
N$207
  Top 0.254: 62.54,36.82 62.54,37.3
N$208
  Top 0.61: 53.65,9.52 53.49,9.52 | 53.65,9.52 54.45,9.52 54.45,8.09 | 53.34,9.52 53.65,9.52 | 53.34,9.52 | 53.34,9.52 53.18,9.36 53.18,6.5 54.13,5.55 57.15,5.55 57.15,6.5 58.57,7.93
N$209
  Top 0.61: 72.86,32.38 73.02,32.54 | 72.86,32.38 72.23,31.74 71.59,32.38 | 77.31,35.71 76.99,35.71 76.99,35.55 74.61,33.17 74.61,32.54 74.45,32.38 72.86,32.38 | 71.59,32.38 72.86,32.38 | 71.59,32.38 69.69,34.28 | 69.69,34.28 | 69.69,34.28 69.53,34.44 71.59,34.44 72.23,35.08
N$210
  Top 0.406: 72.07,35.08 72.07,37.62 72.7,38.25 74.45,38.25
N$211
  Top 1.016: 72.7,37.62 74.45,37.62 | 74.45,37.62 74.92,37.62 | 75.88,38.73 75.56,38.73 74.45,37.62
N$212
  Top 1.016: 72.7,36.98 74.77,36.98
N$213
  Top 1.016: 71.91,32.85 70.64,34.12
N$214
  Top 1.016: 71.11,33.97 72.23,33.97
N$215
  Top 1.016: 74.45,33.65 77.15,36.35
N$216
  Top 1.676: 74.29,34.6 75.88,36.19
N$217
  Top 1.27: 75.56,41.74 74.61,42.7
N$218
  Top 1.016: 54.13,7.93 54.13,8.25 | 54.13,7.14 54.13,7.93 | 54.13,7.14 54.13,6.82 | 54.92,7.14 57.15,7.14 | 54.92,7.14 54.13,7.14 | 54.13,7.93 | 54.92,7.14 54.13,7.93
N$219
  Top 0.61: 71.75,25.39 71.75,27.62
N$220
  Top 0.61: 70.8,26.35 70.8,27.3
N$221
  Top 0.61: 71.27,26.5 71.27,26.82
N$222
  Top 0.61: 70.96,26.19 72.07,25.08 72.7,24.44
  Top 0.813: 72.07,15.71 72.07,25.08
N$223  (via drill 0.8)
  Top 0.254: C36.+ 10.95,7.77 v11.43,8.09 | 64.21,25.95 64.29,25.87 64.29,25.39 v64.29,25.08
  Top 0.406: 78.73,29.2 | 78.42,27.93 78.42,28.89 78.73,29.2
  Top 0.61: 71.59,14.28 72.23,14.28 72.23,13.33 64.45,13.33 64.45,14.12 66.67,16.34 | C12.1 79.72,28.28 79.69,28.25 78.73,29.2 77.52,30.42 IC6.16 | I2C.1 68.52,26.72 IC8.1 70.48,24.44 70.64,24.28 | 68.57,16.82 70.48,16.82 70.64,16.98 70.64,23.96 | 70.64,24.28 70.64,23.96 | 66.67,16.34 67.15,16.82 68.57,16.82 | 66.67,16.34 66.51,16.19 66.51,14.92 67.15,14.28 71.75,14.28 C18.+ | 68.57,16.82 IC8.7 | C18.+ | C18.+ | 63.18,23.49 63.18,25.71 65.72,28.25 66.03,28.25 66.99,27.3 69.05,27.3 69.05,25.87 70.64,24.28 | 64.29,25.39 64.29,24.28 | 70,24.76 70,24.6 70.64,23.96
  Top 0.813: 65.88,27.14 65.4,27.14 64.21,25.95 63.81,25.55 R18.2 63.66,23.64 63.65,23.65 61.74,21.74 61.74,21.58 | 65.88,27.14 67.94,27.14 I2C.1 | 65.88,27.14 | 65.88,27.14 v65.88,27.93
  Top 1.016: R18.2 63.98,23.64 R18.2 | 61.74,21.58 R17.2 | 78.42,27.93 78.42,28.89 | 78.89,24.6 77.78,24.6
  Top 1.27: C36.+ 13.01,8.25 12.86,8.24 U$2.P$2 | 79.69,28.25 80.32,28.25 80.8,27.77 80.8,25.23 | 80.8,25.23 80.8,24.92 80.48,24.6 OC.5 | OC.5 | 78.1,25.23 D5.C | 78.1,25.23 78.73,24.6 78.89,24.6 OC.5 | 78.1,25.23 80.8,25.23
  Top 1.422: 78.1,25.23 78.89,25.23 79.05,25.39 79.05,27.62 v78.73,27.93
  Bottom 0.254: v65.88,27.93 v78.73,27.93 | v11.43,8.09 46.98,7.77 v64.29,25.08
N$224
  Top 0.813: 64.92,13.8 71.75,13.8 | 64.92,13.8 64.77,13.8 | 64.92,13.8 65.88,14.76
N$225
  Top 0.813: 66.19,14.12 66.19,15.39
N$226
  Top 0.813: 65.72,14.28 66.99,14.28
N$227
  Top 0.61: 72.23,16.5 71.91,16.5 71.11,15.71
N$228
  Top 0.61: 63.65,17.93 64.61,18.88 | 60.8,17.93 62.07,17.93 63.65,17.93 | 63.65,17.93 61.11,15.39 60.96,15.39 | IC8.4 66.35,20.63 65.72,20 | 65.72,20 | 64.92,19.2 65.72,20 | 64.92,19.2 | 64.92,19.2 64.45,18.73 61.59,18.73 61.43,18.57 | 61.43,18.57 R17.1 | 61.43,18.57 61.75,17.93 61.11,18.25 | 61.11,18.25 61.43,18.09 | 61.11,18.25 61.11,16.98 61.11,15.71 60.8,15.39 39.68,15.39 39.05,14.76 32.86,14.76 24.6,23.01 24.6,26.5 26.82,28.73 31.27,28.73 32.86,30.31 32.86,32.38 33.17,32.7 IC2.11
  Top 0.813: 61.11,16.98 62.07,17.93
N$229
  Top 0.61: 60.8,18.41 63.65,18.41
N$230
  Top 0.406: 62.38,18.88 62.23,19.04 60.64,19.04 60.64,15.87 60.32,15.55
N$231
  Top 0.61: 48.26,19.68 48.1,19.68 48.89,18.88 50.8,18.88 50.8,19.68
N$232
  Top 0.406: 39.05,42.38 39.05,42.22 38.57,41.74 33.17,41.74
N$233
  Top 0.406: 32.54,41.9 38.41,41.9
N$234
  Top 0.406: 34.44,42.22 33.97,42.22 32.86,41.11 32.86,39.05 31.74,37.93
N$235
  Top 0.305: 43.65,3.01 43.49,3.01 43.49,3.49 43.65,3.49 43.65,2.69
  Top 0.406: 26.51,1.42 26.82,1.74 | 26.51,1.42 30.32,1.42 | 30.32,1.42 30.63,1.74 | 30.32,1.42 39.21,1.42 40.16,2.37 | 26.51,1.42 23.49,4.44 23.17,4.44 23.17,6.03 24.44,6.03 24.44,5.55 | L2.1 45.87,2.85 45.87,3.01 | C38.2 50.8,3.04 50.8,3.01
  Top 0.61: 30.63,1.74 30.79,1.74 | 47.46,3.01 47.78,3.01 48.1,3.33 48.26,3.33 49.68,3.33 50,3.01 50.16,3.01 50.32,3.01 | 26.66,3.49 26.66,2.06 26.98,1.74 | R25.1 | C40.1 25.36,3.67 R23.1
  Top 1.016: 43.65,2.69 | 43.65,2.69 40,2.69 39.05,1.74 35.08,1.74 | 35.08,1.74 34.92,1.74 34.92,3.49 34.93,3.49 R21.2 | 26.66,1.74 | 26.66,1.74 26.82,1.74 26.98,1.74 27.78,1.74 | 30.79,1.74 35.08,1.74 | R23.1 24.44,5.08 26.03,3.49 26.66,3.49 | 26.66,3.49 | 56.35,3.01 R25.1 56.03,3.01 54.61,3.01 50.8,3.01 50.32,3.01 | 43.65,3.01 | 43.65,3.01 R20.2 | 43.65,3.01 45.87,3.01 47.46,3.01
  Top 1.27: 48.26,3.33 50,3.33
N$236
  Top 1.016: 31.59,38.41 31.59,41.59
N$237
  Top 1.016: 32.22,39.05 32.22,41.9
N$238
  Top 1.016: 32.7,41.43 33.33,42.06
N$239
  Top 1.016: 27.62,41.9 30.63,41.9 30.79,42.06
N$240
  Top 1.016: 28.41,41.11 30.95,41.11
N$241
  Top 1.016: 31.11,30.95 31.11,32.7
N$242
  Top 1.016: 30.32,30.47 30.32,32.38
N$243
  Top 1.016: 29.52,30.63 29.52,32.38
N$244
  Top 1.016: 28.57,30.63 28.57,32.38
N$245
  Top 1.016: 14.28,42.86 13.81,42.86 12.38,41.43 12.22,41.27
N$246
  Top 1.016: 12.22,41.27 7.93,41.27 5.87,39.2
N$247
  Top 0.406: 55.56,12.06 55.56,12.22 54.92,12.85
  Top 0.61: 59.05,13.17 59.05,10.79 57.62,10.79 56.83,11.58 55.56,11.58 55.56,12.06 55.56,12.69
N$248
  Top 1.422: 1.58,42.06 11.9,42.06
N$249
  Top 1.422: 5.71,41.27 7.3,41.27
N$250
  Top 1.422: 5.55,38.89 5.55,41.27
N$251
  Top 1.422: 6.5,40.95 6.5,40.79 6.19,40.47
N$252  (via drill 0.8)
  Top 0.254: 44.92,34.12 45.4,33.65 49.53,33.65 50.64,33.65 50.8,33.81
  Top 0.305: 62.7,33.65 62.7,34.92 60.96,34.92 60.96,34.28 60.32,33.65 | 44.92,34.12 44.92,36.35 | 56.19,33.81 53.18,33.81 | v30.63,23.81 30.63,24.28 | 51.43,35.87 51.43,35.71 51.59,35.55 51.75,35.55
  Top 0.406: IC3.8 44.76,34.28 44.92,34.12 45.24,33.81 | 45.24,33.81 | 45.24,33.81 45.4,33.65 49.53,33.65 50.48,33.65 50.8,33.97 | IC4.8 55.88,35.39 55.88,34.12 56.19,33.81 56.35,33.65 56.83,33.65 | C29.2 61.91,33.97 61.59,33.65 60.32,33.65 56.83,33.65 | 56.03,34.12 56.03,33.97 | 56.03,34.12 56.03,36.35 | 56.83,33.65 56.51,33.65 56.03,34.12
  Top 0.61: 21.43,4.6 6.82,4.6 6.19,5.23 | 6.19,5.23 5.23,6.18 | 6.19,5.23 7.93,3.49 21.43,3.49 21.43,5.87 6.82,5.87 6.34,6.34 4.76,6.34 | 55.72,36.19 54.92,35.39 52.07,35.39 51.59,35.87 51.43,35.87 50.16,35.87 50,35.71 50,34.12 49.53,33.65 | IC1.8 21.11,32.85 21.58,33.33 23.33,33.33 | 55.88,34.12 53.34,34.12 C39.+ | 32.38,23.17 | C30.2 32.38,23.17 | IC5.8 32.44,23.23 32.38,23.17 | 6.34,5.71 6.19,5.71 5.55,6.34 4.76,6.34 | 4.76,6.34 0.79,6.34 0.31,6.82 0.31,14.44 | 0.31,14.44 0.31,14.6 1.9,16.19 2.54,16.19 U$1.P$1 | U$1.P$1 | U$1.P$1 | 51.75,35.55 50.8,35.55 | 55.88,35.39 55.24,35.39 | 33.97,22.54 33.81,22.69 31.11,22.69 30.16,23.65 30.16,23.96 30.47,24.28 30.63,24.28 34.13,24.28 34.13,22.54 | 0.31,14.44 0.31,17.14 0.63,17.46 5.55,17.46 5.71,17.61
  Top 1.016: C33.+ 8.09,18.73 v6.82,20.15 | 50.8,33.81 50.8,35.08 v50.48,35.39
  Top 1.27: C31.+ 23.49,33.49 23.33,33.33 | C28.2 50.8,33.97 50.95,33.81 C39.+ | C33.+ 7.29,16.81 U$1.P$1 | 23.33,33.33 | 23.33,33.33 C27.2 | v22.86,31.9 23.33,33.33 | C30.2 31.24,23.3 v30.63,23.81
  Top 1.422: R23.2 6.82,5.23 6.34,5.71 | 5.55,16.98 6.82,18.25 v6.82,20.15 8.25,20.15 8.25,16.03 7.93,15.71 0.95,15.71
  Bottom 0.254: v6.82,20.15 11.74,20.15 v22.86,31.9 v30.63,23.81 30.63,24.12 41.91,35.39 v50.48,35.39
N$253
  Top 0.406: 73.97,17.93 75.88,17.93
N$254
  Top 0.61: 75.4,16.34 75.56,16.34 76.83,15.07 76.83,13.8 78.1,12.53 78.1,7.45 74.77,4.12 65.56,4.12 65.08,3.64 65.08,0.63 64.77,0.31 22.7,0.31 22.54,0.47
N$255
  Top 0.61: 73.97,26.5 | 74.13,26.35 73.97,26.5
N$256
  Top 0.61: 49.53,19.2 49.05,19.2
N$257
  Top 0.305: 40.48,13.17 46.98,13.17 46.98,13.96
N$258
  Top 0.406: 48.57,7.14 47.3,8.41 46.35,8.41 45.87,7.93 45.87,4.91
N$259
  Top 0.61: 59.53,22.38 58.41,21.27 56.99,21.27 56.99,22.54 58.73,22.54
N$260
  Top 0.61: 58.89,22.54 58.41,22.06 58.41,21.74
N$261
  Top 0.305: 56.83,19.84 58.41,19.84 58.41,18.25 56.83,18.25 56.83,19.84
N$262
  Top 1.27: 57.62,12.53 57.62,11.58
N$263
  Top 0.305: 54.61,11.9 53.18,11.9 53.18,10.31 55.08,10.31
N$264
  Top 0.305: C38.1 49.71,5.84 50.16,5.39 52.86,5.39 52.86,5.08 T2.3
  Top 0.406: 48.41,7.3 | 48.41,7.3 49.21,6.5 50,6.5 50,5.55 50.16,5.39
  Top 1.27: L2.2 47.12,7.93 C38.1
N$265
  Top 0.254: 40.48,9.68 44.6,9.68 44.76,9.52 44.76,5.71 44.6,5.55 41.11,5.55 40.32,6.34 40.32,9.52 40.48,9.68
N$266
  Top 0.254: 44.6,5.71 44.6,6.5
N$267
  Top 0.61: 40.64,6.34 41.11,5.87 41.59,5.87
N$268
  Top 0.61: 41.11,6.34 41.43,6.34
N$269
  Top 0.406: 41.75,9.52 43.18,9.52
N$270
  Top 0.61: 17.14,13.17 20.47,9.84 21.43,9.84 21.43,15.55 21.11,15.87 18.09,15.87 16.98,14.76 16.98,13.33 17.14,13.17 | 17.14,13.17
N$271
  Top 0.61: 23.33,15.87 28.09,15.87 28.89,15.07 28.89,14.44 24.28,9.84 23.01,9.84 23.01,15.55 23.33,15.87
N$273
  Top 1.422: 3.17,24.44 6.82,24.44 6.82,23.49
N$274
  Top 1.422: 7.3,19.52 7.3,17.14 6.34,16.19
N$275
  Top 1.422: 5.23,16.98 0.95,16.98 0.95,15.87 0.79,15.71
N$276
  Top 1.422: 2.22,12.38 6.82,12.38
N$277
  Top 0.813: 15.08,10.95 10.47,10.95 10.16,11.26 10.16,26.19 9.36,26.98
N$278
  Top 1.422: 23.97,10.47 27.78,14.28
N$279
  Top 1.422: 24.12,11.74 26.35,13.96
N$280
  Top 1.422: 25.39,14.12 24.92,14.12 23.97,13.17
N$281
  Top 1.422: 17.62,14.44 17.62,13.8 20.47,10.95
N$282
  Top 1.422: 20.31,12.69 18.73,14.28
N$283
  Top 1.422: 20.16,14.28 20.16,14.12 20,13.96
N$284
  Top 1.422: 16.5,9.04 16.5,8.72 17.3,7.93
N$285
  Top 1.422: 17.14,21.9 22.22,21.9 | 17.14,21.9 17.14,21.74 | 17.14,18.09 17.14,21.9
N$286
  Top 1.422: 23.65,19.68 23.65,18.41 25.08,18.41 25.24,18.25
N$287
  Top 1.422: 18.09,22.22 18.09,22.06 16.82,20.79
N$288
  Top 1.422: 16.82,18.41 17.14,18.41 17.77,17.77
N$289
  Top 0.406: 25.39,4.44 27.3,4.44 27.46,4.28 27.46,2.53 28.25,1.74
N$290
  Top 0.406: 27.78,2.22 arc111 30.47,2.06
N$291
  Top 1.016: 23.97,4.6 26.35,2.22
N$292
  Top 1.016: 27.14,3.17 27.14,2.37
N$293
  Top 0.813: 22.7,2.85 24.92,0.63 22.86,0.63 22.86,2.22
N$294
  Top 0.813: 23.49,1.58 23.49,1.1 23.65,0.95
N$295
  Top 0.406: 28.41,3.49 28.41,4.91
N$296
  Top 0.406: 29.2,5.23 29.2,5.07 30,4.28 31.9,4.28 31.9,3.01 29.52,3.01
N$297
  Top 0.305: 47.62,2.53 | 47.46,2.37 47.62,2.53 | 47.46,2.37
N$298
  Top 0.305: 57.3,2.53 57.3,3.8
N$299
  Top 1.016: 54.29,3.49 55.72,3.49
N$300
  Top 0.305: 49.53,3.49 49.21,3.49 | 49.53,3.49 53.81,3.49 | 49.53,3.49 44.92,3.49 44.45,3.96 44.45,3.64 44.6,3.49
N$301
  Top 0.305: 43.81,2.37 47.3,2.37
N$302
  Top 0.305: 41.91,3.01 42.86,3.96
N$303
  Top 0.61: 42.7,3.49 42.7,3.17 42.38,3.17
N$304
  Top 0.406: 52.22,5.23 51.91,4.91
N$307
  Top 0.406: 40.16,5.23 40.64,4.76
N$308
  Top 0.406: 42.38,4.76 42.06,4.76 41.27,3.96 39.21,3.96
N$309
  Top 0.61: 40.16,4.44 41.43,4.44
N$310
  Top 0.61: 39.68,4.44 39.68,4.28 38.57,3.17 36.98,3.17 36.98,4.6 39.05,4.6 39.52,5.07
N$311
  Top 0.61: 36.35,1.9 35.55,2.69 35.55,4.6 33.49,4.6 33.33,4.44 33.33,2.53 32.7,1.9
N$312
  Top 0.61: 35.55,2.37 34.76,2.37
N$313
  Top 0.813: 33.97,2.22 33.97,4.28
N$314
  Top 0.813: 34.29,3.01 34.29,2.37
N$315
  Top 0.813: 33.81,2.53 33.81,2.22 33.65,2.06
N$316
  Top 0.61: 37.46,6.5 37.14,6.82 34.76,6.82 33.81,7.77 31.11,7.77 30.47,7.14 30.47,5.71 37.62,5.71 37.62,6.34 37.46,6.5 | 37.46,6.5
N$317
  Top 0.61: 32.22,7.3 31.27,7.3 | 32.22,7.3 32.38,7.3 | 32.22,7.3 31.9,6.98
N$318
  Top 0.61: 33.33,7.3 33.97,7.3
N$319
  Top 0.61: 33.49,6.98 34.44,6.98
N$320
  Top 0.406: 38.57,6.34 38.57,6.82 | 38.57,6.34 39.21,6.34 39.21,9.99 | 38.57,6.34 38.57,7.3 37.78,8.09 35.55,8.09 35.4,8.25 35.4,9.68 35.55,9.84 38.73,9.84 | 39.21,9.99 | 39.21,9.99 39.52,10.31 42.06,10.31 42.06,11.58 40.48,11.58 38.57,9.68
N$321
  Top 0.406: 40.79,11.11 40.32,11.11
N$322
  Top 0.305: 50.48,11.26 50.48,11.9 51.91,11.9 51.91,11.74 51.91,6.82
  Top 0.406: 51.91,6.34 51.91,6.5 | 51.91,6.34 51.27,6.34 51.27,7.3 49.53,9.04 49.37,9.2 48.1,9.2 48.1,10.47 48.26,10.63 49.84,10.63 50.48,11.26 | 51.91,11.74 51.91,6.34
N$323
  Top 0.406: 50.64,11.11 50.64,10.95 50,10.31
N$324
  Top 0.813: 49.84,9.84 49.84,9.36 51.43,7.77
N$325
  Top 0.406: 50.48,12.85 50.16,12.85 50,12.85 49.68,12.53 49.68,11.9 49.53,11.74 47.62,11.74
  Top 0.61: 50.16,12.85 49.53,12.22
N$326
  Top 0.406: 46.98,10.95 46.98,10.31 45.4,10.31 | 45.4,10.31 | 44.6,11.11 45.4,10.31
N$327
  Top 0.305: 57.3,2.37 | 57.3,2.37 57.15,2.22 39.84,2.22
N$328
  Top 1.422: 32.06,10.79 33.33,10.79
N$329
  Top 1.422: 31.74,12.22 31.43,12.22 27.93,8.72 27.93,8.57 26.98,7.61
N$330
  Top 1.422: 27.93,6.98 27.93,8.41
N$331
  Top 1.016: 7.77,3.96 20.95,3.96
N$332
  Top 0.61: 58.89,1.9 58.89,4.12 59.21,4.44 64.92,4.44 | 64.92,4.44 66.51,4.44 | 64.92,4.44 arc180 64.92,7.77 62.38,7.77 62.07,8.09 62.07,10.47 63.5,11.9 73.34,11.9 74.45,13.01
N$333
  Top 1.27: 73.02,16.19 72.7,16.19 | 73.02,16.19 75.08,16.19 | 73.02,16.19 73.18,16.19 74.61,14.76
N$334
  Top 1.27: 74.45,12.38 74.45,15.87
N$335
  Top 1.27: 75.4,15.87 | 75.88,15.39 75.4,15.87
N$336
  Top 1.27: 76.83,13.01 77.46,12.38 76.83,12.38
N$337
  Top 1.27: 77.31,7.93 77.31,7.77 74.77,5.23
N$338
  Top 1.27: 76.19,7.61 75.88,7.61 74.92,6.66
N$339
  Top 1.27: 63.02,8.41 63.02,10.79
N$340
  Top 1.27: 62.54,8.25 62.54,10.31
N$341
  Top 1.27: 65.88,8.72 65.88,8.57 67.15,7.3
N$342
  Top 1.27: 37.78,8.57 38.1,8.57 38.57,8.09
N$343
  Top 1.676: 30.95,12.85 36.51,12.85
N$344
  Top 1.016: 76.04,27.3 75.08,28.25
N$345
  Top 1.016: 60.32,27.14 59.69,27.14
N$346
  Top 1.016: 50.95,25.71 | 50.95,25.71 52.7,23.96
N$347
  Top 0.61: 15.08,41.11 19.52,41.11
N$348
  Top 0.61: 38.57,26.5 38.57,32.06
N$349
  Top 0.61: 47.62,2.37 56.99,2.37
N$350
  Top 0.61: 48.73,2.85 47.78,2.85
N$351
  Top 1.016: 46.35,5.23 46.35,7.93
N$352
  Top 1.016: 47.14,5.23 47.14,7.14
N$353
  Top 0.813: 47.78,5.07 47.78,6.5
N$354
  Top 0.813: 48.26,5.87 48.26,5.07 51.91,5.07
(copper drawn outside any net)
  shapes: Top area x27

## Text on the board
Top: AD | 2009 | Slomkowski | Michal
